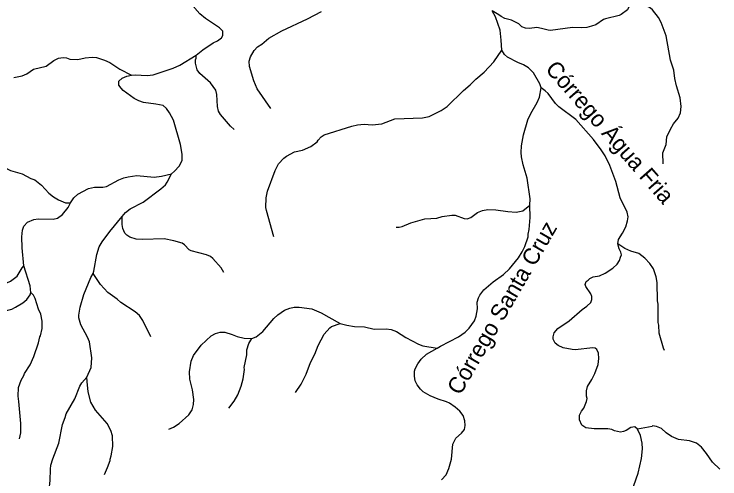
# Model space of a CAD drawing. Extents: x 500 to 555.2, y 9115.7 to 9171.
# Drawn here: x 534.85 to 543.46, y 9156.16 to 9161.84 of the extents above; entities that cross this region are included whole.
import ezdxf
from ezdxf.enums import TextEntityAlignment as Align

# ---------------------------------------------------------------- set-up
doc = ezdxf.new("R2010")
doc.units = 0
doc.header["$LTSCALE"] = 0.064
doc.layers.add('61', color=7, linetype='Continuous')
doc.layers.add('7', color=7, linetype='Continuous', lineweight=25)

msp = doc.modelspace()

# ---------------------------------------------------------------- linework, layer by layer
at = {"layer": '7'}
for points in [[(537.0694, 9161.3359), (537.1514, 9161.4018), (537.2796, 9161.4867), (537.3299, 9161.5121), (537.3789, 9161.5484), (537.3966, 9161.5747), (537.3964, 9161.6271), (537.3556, 9161.6674), (537.1827, 9161.7822), (537.115, 9161.8409), (537.0546, 9161.91), (536.9997, 9162.0076)], [(542.357, 9161.9325), (542.3358, 9161.8881), (542.2601, 9161.8333), (542.2324, 9161.8211), (542.0693, 9161.7804), (542.0431, 9161.7689), (541.9484, 9161.707), (541.8973, 9161.6877), (541.8409, 9161.6743), (541.7746, 9161.6692), (541.6624, 9161.6724), (541.3947, 9161.6381), (541.3672, 9161.6398), (541.2852, 9161.6628), (541.2282, 9161.6723), (541.1381, 9161.6627), (541.0913, 9161.6643), (541.047, 9161.6817), (541.0103, 9161.7182), (540.9189, 9161.764), (540.8403, 9161.7839), (540.7917, 9161.8063), (540.7658, 9161.8283), (540.6848, 9161.8761)], [(542.7702, 9160.0104), (542.7667, 9160.1419), (542.8061, 9160.2443), (542.8168, 9160.3391), (542.8594, 9160.4332), (542.8966, 9160.498), (542.9542, 9160.5675), (542.9818, 9160.6332), (542.9901, 9160.7077), (542.9801, 9160.813), (542.9325, 9160.9613), (542.9132, 9161.0509), (542.8996, 9161.1516), (542.8589, 9161.2756), (542.8092, 9161.5723), (542.7489, 9161.7348), (542.7145, 9161.7971), (542.6428, 9161.8868), (542.6176, 9161.9103), (542.557, 9161.9464), (542.5193, 9161.9594), (542.4897, 9161.9611), (542.357, 9161.9325)], [(537.9819, 9160.6852), (537.8153, 9160.9259), (537.7744, 9161.0228), (537.7232, 9161.1963), (537.7182, 9161.2635), (537.7332, 9161.3155), (537.7769, 9161.393), (537.8207, 9161.4354), (537.8706, 9161.4691), (537.9588, 9161.5409), (538.1153, 9161.6325), (538.4279, 9161.7805), (538.6006, 9161.8693)], [(540.8024, 9161.3973), (540.7952, 9161.5165), (540.7805, 9161.6397), (540.7239, 9161.8021), (540.6848, 9161.8761)], [(536.2806, 9161.092), (536.3267, 9161.0945), (536.4739, 9161.087), (536.5438, 9161.0949), (536.7875, 9161.175), (536.8718, 9161.2145), (537.0694, 9161.3359)], [(537.5354, 9160.426), (537.4878, 9160.4675), (537.3656, 9160.6097), (537.3435, 9160.6504), (537.3308, 9160.7102), (537.3212, 9160.8556), (537.3095, 9160.9062), (537.2435, 9160.9988), (537.1133, 9161.111), (537.0819, 9161.1571), (537.0621, 9161.2394), (537.0635, 9161.2775), (537.0701, 9161.2986), (537.0694, 9161.3359)], [(538.0193, 9159.118), (537.9279, 9159.4397), (537.9216, 9159.4778), (537.9263, 9159.5946), (537.9402, 9159.6767), (538.0329, 9159.9267), (538.0762, 9160.0097), (538.14, 9160.0772), (538.1726, 9160.1032), (538.2715, 9160.1537), (538.3699, 9160.1752), (538.468, 9160.2202), (538.5485, 9160.2757), (538.5577, 9160.2959), (538.595, 9160.3374), (538.6335, 9160.3635), (538.9698, 9160.4669), (539.038, 9160.4832), (539.1206, 9160.4931), (539.2196, 9160.485), (539.3358, 9160.4963), (539.4941, 9160.5586), (539.8336, 9160.5716), (539.9155, 9160.5886), (540.0626, 9160.6616), (540.1329, 9160.7092), (540.3356, 9160.906), (540.4164, 9160.9738), (540.4848, 9161.0435), (540.5874, 9161.1283), (540.7051, 9161.2526), (540.8024, 9161.3973)], [(541.2819, 9160.9352), (541.2646, 9160.9839), (541.1873, 9161.1181), (541.1288, 9161.1799), (541.0645, 9161.2172), (540.9958, 9161.2467), (540.8722, 9161.3108), (540.8358, 9161.3429), (540.8025, 9161.3954), (540.8024, 9161.3973)], [(534.846, 9161.0639), (534.945, 9161.0822), (535.0015, 9161.107), (535.085, 9161.166), (535.2386, 9161.1995), (535.3338, 9161.2699), (535.3896, 9161.2984), (535.4476, 9161.3066), (535.4857, 9161.3017), (535.5264, 9161.2885), (535.6236, 9161.2821), (535.7147, 9161.3015), (535.8007, 9161.3117), (535.8537, 9161.3066), (535.9521, 9161.2752), (536.0155, 9161.2444), (536.138, 9161.166), (536.2806, 9161.092)], [(536.7686, 9159.8886), (536.8066, 9159.9184), (536.8615, 9159.9792), (536.8979, 9160.051), (536.9012, 9160.1288), (536.8783, 9160.2454), (536.7915, 9160.5401), (536.7463, 9160.6306), (536.7065, 9160.6845), (536.6683, 9160.7193), (536.5764, 9160.739), (536.4273, 9160.7557), (536.3683, 9160.7775), (536.3115, 9160.8077), (536.1803, 9160.903), (536.1527, 9160.9316), (536.1272, 9160.9695), (536.1257, 9161.0179), (536.1687, 9161.0531), (536.2254, 9161.0792), (536.2806, 9161.092)], [(541.1446, 9159.5052), (541.1446, 9159.5064), (541.1478, 9159.5812), (541.1102, 9159.8354), (541.0637, 9159.9953), (541.0437, 9160.0939), (541.0382, 9160.1489), (541.0398, 9160.229), (541.0665, 9160.3627), (541.1187, 9160.5446), (541.1549, 9160.6233), (541.2325, 9160.7574), (541.2599, 9160.8209), (541.2819, 9160.9352)], [(542.2187, 9159.0341), (542.2275, 9159.0849), (542.2765, 9159.1629), (542.3142, 9159.2416), (542.3376, 9159.3152), (542.342, 9159.3604), (542.3338, 9159.4187), (542.2456, 9159.5953), (542.1926, 9159.7934), (542.1221, 9159.9902), (542.0624, 9160.1062), (542.014, 9160.1816), (541.9194, 9160.304), (541.7036, 9160.5492), (541.4971, 9160.7061), (541.4569, 9160.7438), (541.3678, 9160.8655), (541.3316, 9160.8999), (541.2819, 9160.9352)], [(534.4269, 9160.0956), (534.4843, 9160.0248), (534.519, 9160.0022), (534.5907, 9159.9781), (534.6663, 9159.9797), (534.7175, 9159.9714), (534.8034, 9159.9256), (534.9477, 9159.8878), (535.0533, 9159.8318), (535.0986, 9159.8155), (535.1827, 9159.7496), (535.2727, 9159.6514), (535.3267, 9159.6042), (535.39, 9159.5691), (535.4764, 9159.5322), (535.5355, 9159.5345)], [(533.6703, 9159.9427), (533.7132, 9159.926), (533.7623, 9159.8919), (533.8356, 9159.8255), (533.9122, 9159.7243), (533.9807, 9159.5979), (534.0426, 9159.5215), (534.1259, 9159.4023), (534.1537, 9159.3531), (534.1651, 9159.3176), (534.2187, 9159.21), (534.2816, 9159.0355), (534.375, 9158.819), (534.4356, 9158.7107), (534.518, 9158.6215), (534.5527, 9158.5937), (534.6366, 9158.5592), (534.6821, 9158.5527), (534.7569, 9158.5574), (534.8035, 9158.5783), (534.8837, 9158.6397), (534.9464, 9158.7396), (534.9652, 9158.7655)], [(535.5355, 9159.5345), (535.5769, 9159.5935), (535.6268, 9159.6384), (535.7576, 9159.7078), (535.8302, 9159.7238), (535.93, 9159.724), (535.9742, 9159.7326), (536.1255, 9159.8123), (536.1865, 9159.8382), (536.2402, 9159.8517), (536.3459, 9159.8648), (536.5571, 9159.8462), (536.6451, 9159.857), (536.7678, 9159.888), (536.7686, 9159.8886)], [(536.1681, 9159.3681), (536.2071, 9159.4151), (536.2652, 9159.4605), (536.4234, 9159.5414), (536.6399, 9159.7054), (536.6941, 9159.7529), (536.7163, 9159.7834), (536.7686, 9159.8886)], [(534.9652, 9158.7655), (534.9445, 9158.9851), (534.9429, 9159.1183), (534.9499, 9159.1981), (534.9672, 9159.2475), (535.0115, 9159.2986), (535.0864, 9159.3278), (535.1412, 9159.3383), (535.3257, 9159.3351), (535.3786, 9159.3457), (535.4387, 9159.3915), (535.507, 9159.4779), (535.5355, 9159.5345)], [(539.5102, 9159.2341), (539.5471, 9159.2341), (539.5831, 9159.2433), (539.692, 9159.2893), (539.8633, 9159.3386), (540.0084, 9159.3464), (540.074, 9159.3644), (540.1933, 9159.3826), (540.2319, 9159.381), (540.3402, 9159.3421), (540.3779, 9159.3369), (540.4238, 9159.3553), (540.5065, 9159.4152), (540.5641, 9159.4384), (540.6296, 9159.4515), (540.7276, 9159.4483), (540.8757, 9159.4253), (540.9769, 9159.4188), (541.0567, 9159.4355), (541.1446, 9159.5052)], [(540.0106, 9157.7594), (540.0518, 9157.7834), (540.271, 9157.8986), (540.3552, 9157.9552), (540.4043, 9158.0027), (540.466, 9158.091), (540.4865, 9158.151), (540.5032, 9158.2404), (540.5021, 9158.3194), (540.5164, 9158.3716), (540.5349, 9158.4056), (540.5833, 9158.4701), (540.6948, 9158.5674), (540.8221, 9158.6583), (540.8942, 9158.7255), (541.004, 9158.8616), (541.0512, 9158.9333), (541.084, 9158.9988), (541.1212, 9159.1177), (541.1219, 9159.1504), (541.1347, 9159.2082), (541.1496, 9159.3558), (541.1446, 9159.5052)], [(535.8114, 9158.6687), (535.8213, 9158.7), (535.8593, 9158.9022), (535.8851, 9158.9963), (535.9208, 9159.0585), (536.0151, 9159.1836), (536.1681, 9159.3681)], [(537.4072, 9158.6824), (537.3739, 9158.7391), (537.275, 9158.8546), (537.2457, 9158.8758), (537.1954, 9158.8985), (537.0087, 9158.9475), (536.9855, 9158.9608), (536.9285, 9159.021), (536.8981, 9159.0387), (536.7961, 9159.0682), (536.6793, 9159.0939), (536.4168, 9159.0842), (536.3381, 9159.0908), (536.2587, 9159.1144), (536.2225, 9159.1386), (536.1986, 9159.1636), (536.175, 9159.218), (536.1682, 9159.2672), (536.1681, 9159.3681)], [(542.7888, 9157.7294), (542.775, 9157.7569), (542.7208, 9157.9412), (542.7177, 9158.0382), (542.7114, 9158.0705), (542.7111, 9158.2979), (542.7014, 9158.3363), (542.698, 9158.562), (542.6862, 9158.6293), (542.6536, 9158.7264), (542.6074, 9158.7943), (542.5487, 9158.8594), (542.4732, 9158.9135), (542.3759, 9158.9442), (542.3017, 9158.9742), (542.2187, 9159.0341)], [(542.2559, 9158.9325), (542.2334, 9158.9701), (542.2187, 9159.0341)], [(542.4565, 9156.7713), (542.4562, 9156.772), (542.4256, 9156.7972), (542.375, 9156.7891), (542.3209, 9156.7527), (542.2863, 9156.7402), (542.2497, 9156.7354), (542.1788, 9156.7482), (542.1442, 9156.7644), (542.0961, 9156.7761), (541.9282, 9156.7746), (541.8266, 9156.7881), (541.7801, 9156.8185), (541.7519, 9156.8822), (541.7515, 9156.9405), (541.7763, 9156.9911), (541.8027, 9157.0262), (541.837, 9157.1066), (541.8419, 9157.146), (541.8337, 9157.1721), (541.8336, 9157.2365), (541.8466, 9157.2906), (541.9017, 9157.3768), (541.9383, 9157.4498), (541.9761, 9157.558), (541.9878, 9157.6308), (541.9806, 9157.6982), (541.9627, 9157.7441), (541.9418, 9157.757), (541.9139, 9157.7634), (541.6976, 9157.7391), (541.6602, 9157.7412), (541.552, 9157.7646), (541.4892, 9157.79), (541.4544, 9157.8184), (541.4287, 9157.8704), (541.4288, 9157.8972), (541.4404, 9157.9462), (541.4838, 9157.9994), (541.6237, 9158.0918), (541.7807, 9158.2291), (541.8381, 9158.2698), (541.8874, 9158.3182), (541.8991, 9158.3532), (541.8987, 9158.3901), (541.8873, 9158.422), (541.8254, 9158.5115), (541.8201, 9158.5377), (541.8225, 9158.5493), (541.8329, 9158.571), (541.8544, 9158.5889), (541.8765, 9158.6094), (541.9175, 9158.63), (541.9944, 9158.6429), (542.0639, 9158.676), (542.1556, 9158.7368), (542.2081, 9158.7861), (542.238, 9158.8274), (542.2523, 9158.8714), (542.261, 9158.8991), (542.2559, 9158.9325)], [(535.0518, 9158.4402), (535.0483, 9158.4792), (535.0427, 9158.5213), (534.9652, 9158.7655)], [(535.7346, 9157.4046), (535.788, 9157.5219), (535.7973, 9157.6406), (535.7695, 9157.8342), (535.7445, 9157.8941), (535.6631, 9158.0436), (535.6391, 9158.1285), (535.6383, 9158.1623), (535.6531, 9158.2574), (535.7002, 9158.4135), (535.7853, 9158.6202), (535.8114, 9158.6687)], [(536.5152, 9157.8969), (536.4209, 9158.0961), (536.3764, 9158.1557), (536.3239, 9158.2032), (536.1511, 9158.3154), (536.1069, 9158.3562), (535.993, 9158.4391), (535.9015, 9158.5374), (535.8114, 9158.6687)], [(534.3994, 9158.0562), (534.4474, 9158.1003), (534.5356, 9158.1545), (534.6105, 9158.1821), (534.8191, 9158.236), (534.8657, 9158.2575), (534.954, 9158.3118), (535.0034, 9158.3528), (535.0454, 9158.4104), (535.0518, 9158.4402)], [(534.9124, 9156.6525), (534.9279, 9156.7243), (534.9313, 9156.8399), (534.9066, 9157.1071), (534.8953, 9157.1721), (534.9002, 9157.2806), (534.9351, 9157.3696), (534.967, 9157.4237), (534.9757, 9157.4486), (535.0445, 9157.5554), (535.0885, 9157.6566), (535.1459, 9157.8257), (535.16, 9157.897), (535.1692, 9157.9088), (535.1903, 9157.9983), (535.1903, 9158.0883), (535.1726, 9158.1748), (535.1456, 9158.2359), (535.105, 9158.3657), (535.0826, 9158.4078), (535.0518, 9158.4402)], [(537.751, 9157.8786), (537.8034, 9157.8986), (537.8838, 9157.9606), (538.0168, 9158.1229), (538.0654, 9158.1668), (538.1489, 9158.2242), (538.2117, 9158.2479), (538.2677, 9158.259), (538.3267, 9158.2606), (538.4809, 9158.2377), (538.5966, 9158.1914), (538.6889, 9158.1353), (538.8276, 9158.0618)], [(538.2846, 9157.2191), (538.3516, 9157.3198), (538.4133, 9157.44), (538.4674, 9157.5821), (538.5199, 9157.6861), (538.5615, 9157.7921), (538.6341, 9157.9287), (538.6999, 9158.0055), (538.7237, 9158.0228), (538.8276, 9158.0618)], [(538.8276, 9158.0618), (538.8281, 9158.0615), (538.9091, 9158.0379), (539.0019, 9158.0245), (539.1233, 9158.0196), (539.2427, 9157.9916), (539.3896, 9157.9949), (539.4526, 9157.9881), (539.5157, 9157.9614), (539.6311, 9157.8891), (539.7825, 9157.8069), (539.8384, 9157.7884), (540.0106, 9157.7594)], [(536.7364, 9156.7715), (536.7925, 9156.7966), (536.8622, 9156.8406), (536.9796, 9156.9464), (537.0215, 9157.007), (537.0375, 9157.0704), (537.0407, 9157.1322), (537.0242, 9157.2509), (536.9948, 9157.3816), (536.9868, 9157.4684), (537.0081, 9157.5994), (537.0394, 9157.6707), (537.1299, 9157.7972), (537.2531, 9157.9083), (537.3081, 9157.9391), (537.3629, 9157.9555), (537.4219, 9157.9538), (537.5098, 9157.9277), (537.5704, 9157.8994), (537.6581, 9157.8801), (537.751, 9157.8786)], [(537.4698, 9157.0262), (537.5327, 9157.1126), (537.5803, 9157.1912), (537.6199, 9157.2935), (537.6441, 9157.3842), (537.659, 9157.499), (537.6576, 9157.5225), (537.6901, 9157.6773), (537.6894, 9157.739), (537.7133, 9157.8145), (537.751, 9157.8786)], [(540.0648, 9156.1526), (540.1209, 9156.2122), (540.1548, 9156.2883), (540.1882, 9156.4033), (540.2037, 9156.5858), (540.2398, 9156.6599), (540.3087, 9156.7194), (540.3441, 9156.7664), (540.3556, 9156.814), (540.3506, 9156.8736), (540.3306, 9156.9375), (540.2884, 9156.9911), (540.2327, 9157.0403), (540.1621, 9157.0862), (540.1251, 9157.104), (540.0261, 9157.1372), (539.9263, 9157.1788), (539.8419, 9157.2266), (539.8075, 9157.2574), (539.7672, 9157.3097), (539.7439, 9157.3585), (539.7358, 9157.417), (539.7364, 9157.4792), (539.7441, 9157.5066), (539.7746, 9157.5691), (539.8149, 9157.6231), (539.8838, 9157.6856), (540.0106, 9157.7594)], [(535.2396, 9155.3658), (535.3051, 9155.6265), (535.32, 9155.7412), (535.3117, 9155.8232), (535.2808, 9155.9211), (535.2758, 9156.0279), (535.2888, 9156.1447), (535.2906, 9156.2805), (535.2977, 9156.3304), (535.3201, 9156.4098), (535.3923, 9156.5997), (535.4366, 9156.8271), (535.4724, 9156.9124), (535.484, 9156.9579), (535.589, 9157.1388), (535.6482, 9157.2962), (535.6731, 9157.3359), (535.7346, 9157.4046)], [(535.9496, 9156.2181), (535.9889, 9156.301), (536.0186, 9156.3861), (536.0189, 9156.4047), (536.0322, 9156.4445), (536.0516, 9156.5581), (536.0485, 9156.6881), (536.0298, 9156.7559), (535.984, 9156.8374), (535.8421, 9157.0021), (535.7843, 9157.0995), (535.75, 9157.2267), (535.7402, 9157.3528), (535.7346, 9157.4046)], [(542.3744, 9155.8681), (542.3995, 9155.9808), (542.4137, 9156.0836), (542.4647, 9156.2319), (542.5078, 9156.4104), (542.5209, 9156.5312), (542.5158, 9156.5981), (542.4946, 9156.6914), (542.4565, 9156.7713)], [(543.4637, 9156.2832), (543.3741, 9156.3679), (543.3017, 9156.4728), (543.2382, 9156.5507), (543.1764, 9156.5976), (543.094, 9156.6268), (542.9589, 9156.6451), (542.8744, 9156.6826), (542.808, 9156.7271), (542.7528, 9156.7763), (542.6898, 9156.8041), (542.6406, 9156.8089), (542.6358, 9156.804), (542.4565, 9156.7713)]]:
    msp.add_lwpolyline(points, dxfattribs=at)

# ---------------------------------------------------------------- texts
at = {"layer": '61'}
for s, rotation, p in [('Córrego Água Fria', 311.186, (542.0473, 9160.3316)), ('Córrego Santa Cruz', 59.982, (540.8894, 9158.2036))]:
    msp.add_text(s, height=0.2, rotation=rotation, dxfattribs=at).set_placement(p, align=Align.CENTER)

doc.saveas('drawing.dxf')
